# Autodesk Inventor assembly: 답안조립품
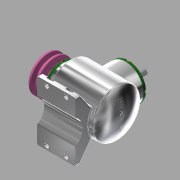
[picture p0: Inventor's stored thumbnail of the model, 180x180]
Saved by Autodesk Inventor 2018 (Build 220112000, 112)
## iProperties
Created: 2021-04
Part Number: 답안조립품
Material: 일반
Document SubType Name: Assembly
Designer: home
Author: home
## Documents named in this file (17)
- C:\Users\home\Desktop\710407V1016\답안조립품.iam
- C:\Users\home\Desktop\710407V1016\본체.ipt
- C:\Users\home\Desktop\710407V1016\커버.ipt
- C:\Users\home\Desktop\710407V1016\베어링 6203.ipt
- C:\Users\home\Desktop\710407V1016\오일실 17 x 32 x 8.ipt
- C:\Users\home\Desktop\710407V1016\메인 축.ipt
- 메인 축.ipt
- C:\Users\home\Desktop\710407V1016\서브 축.ipt
- 서브 축.ipt
- C:\Users\home\Desktop\710407V1016\키 5 x 5 x 14.ipt
- C:\Users\home\Desktop\710407V1016\키 4 x 4 x 14.ipt
- C:\Users\home\Desktop\710407V1016\메인 베벨기어.ipt
- C:\Users\home\Desktop\710407V1016\서브 베벨기어.ipt
- C:\Users\home\Desktop\710407V1016\V-벨트풀리.ipt
- C:\Users\home\Desktop\710407V1016\육각볼트 M4 x 8.ipt
- C:\Users\home\Desktop\710407V1016\와셔 4 x 16.ipt
- C:\Users\home\Desktop\710407V1016\볼트 M4 x 10.ipt
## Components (1 placed, 1 different names)
1. V-벨트풀리:1 — 각도:6
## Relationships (1: Angle 1)
- 각도:6 [Angle]: V-벨트풀리:1
